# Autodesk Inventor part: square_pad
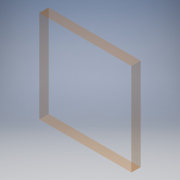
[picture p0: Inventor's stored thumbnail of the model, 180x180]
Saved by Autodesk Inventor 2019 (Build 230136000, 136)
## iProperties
Created: 2020-02
Part Number: square_pad
Material: Generic
Document SubType Name: Modeling
Designer: Siddharth
Density: 1 g/cm^3
Appearance: Default
Author: Siddharth
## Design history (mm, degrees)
sketch "Sketch1"
  geometry: L1 (0, 0)-(100, 0); L2 (100, 0)-(100, 100); L3 (100, 100)-(0, 100); L4 (0, 100)-(0, 0)
  constraints: 8 end point, 2 parallel, 1 horizontal, 1 perpendicular
  dimensions: "d0" = 100 distance of L3.end L2.end; "d1" = 100 distance of L2.end L1.end
extrude_surface "ExtrusionSrf1" sketch "Sketch1" dims "d7" = 10, "d8" = 0
body "Solid1"
body "Srf1"
